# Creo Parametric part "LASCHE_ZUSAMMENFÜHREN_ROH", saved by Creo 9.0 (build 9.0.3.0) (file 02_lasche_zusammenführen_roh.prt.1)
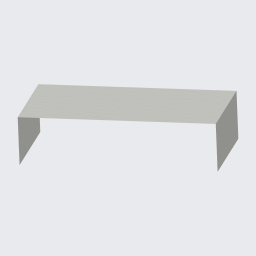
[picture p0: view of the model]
Units: millimeter Kilogram Sec (mmKs); MM, KILOGRAM, SECS
Materials in the file: S235JRG2

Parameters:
  BENENNUNG = "XXX"
  DATUM = "XX.XX.XX"
  ERSTELLER = "ARINDA"
  TEILETYP = "Fertigungsteil"
  SELECT_EN_NAME = "S235JRG2"
  SELECT_DIN_NAME = "RSt37-2"
  SELECT_DIN_NUMBER = "1.0038"
  SELECT_ASTM_NAME = "A 283 M Grade 2"
  MATERIAL_GROUP = "ME_ST_Baustahl"
  STANDARD_EN_DELIVERYSPEC = "DIN EN 10025"
  STANDARD_DIN_DELIVERYSPEC = "DIN 17100"

Other parameters: MASSE

Created from: ARINDA-STARTTEIL.PRT

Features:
  1. coordinate system "CS0"
  2. datum plane "DTM1", "T_RECHTS_Y-Z"
  3. datum plane "DTM2", "T_OBEN_X-Z"
  4. datum plane "DTM3", "T_VORNE_X-Y"
  5. datum axis "T_X-ACHSE"
  6. datum axis "A_1"
  7. datum axis "A_2"
  8. feature "Profil 1"

Other named items: T_BASIC, T_Y-ACHSE, T_Z-ACHSE

Layers: 00_STD-ACHSEN, 00_STD-EBENEN, 00_STD-KOORDSYS, FLAECHEN, SAMMELFLÄCHEN

Surfaces: 5 plane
